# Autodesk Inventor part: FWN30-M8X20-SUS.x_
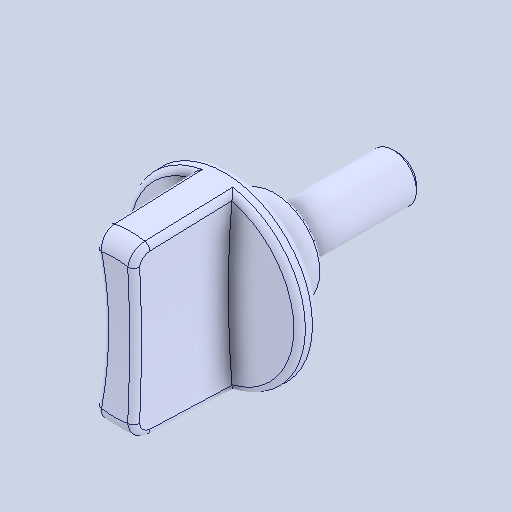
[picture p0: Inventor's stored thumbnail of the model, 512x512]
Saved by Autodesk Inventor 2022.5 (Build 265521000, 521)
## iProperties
Created: 2024-05
Part Number: FWN30-M8X20-SUS.x_
Material: 一般
Document SubType Name: Modeling
Designer: ImaoCorp
Density: 1 g/cm^3
Appearance: 既定
Author: ImaoCorp
Sending System: SOLIDWORKS 2022-2022290
MC: AMD64
MC_MODEL: Intel64 Family 6 Model 60 Stepping 3, GenuineIntel
OS: Windows_NT
FRU: Parasolid Version 33.1, build 260,  4-25-2022
FORMAT: text
GUISE: transmit
KEY: FILEFWN30-M8X20-SUS.x_t
DATE: Mon May 20 16:40:26 2024
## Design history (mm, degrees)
feature "Base1"
node "ソリッド1"
